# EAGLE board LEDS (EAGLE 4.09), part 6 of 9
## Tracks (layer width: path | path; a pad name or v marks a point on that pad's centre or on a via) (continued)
N$X.1430  (via drill 0.2)  (1 unrouted) (continued)
  Bottom 0.2: 39.44,35.76 38.85,36.35 38.41,36.35
  other vias: 39.44,35.83
N$X.1460  (via drill 0.2)  (1 unrouted)
  Bottom 0.2: 37.6,33.1 36.89,33.8 36.35,33.8
  other vias: 37.62,33.16
N$X.1461  (via drill 0.2)  (1 unrouted)
  Bottom 0.2: 37.53,35.8 36.89,36.44 36.63,36.44
  other vias: 37.57,35.78
N$X.1482  (via drill 0.2)  (1 unrouted)
  Bottom 0.2: 32.15,75 31.14,75.54 30.79,75.54
  other vias: 32.19,74.95
N$X.1491  (via drill 0.2)  (1 unrouted)
  Bottom 0.2: v35.82,33.14 35.14,33.83 34.72,33.83
N$X.1492  (via drill 0.2)  (1 unrouted)
  Bottom 0.2: v35.8,35.8 35.23,36.37 34.79,36.37
N$X.1522  (via drill 0.2)  (1 unrouted)
  Bottom 0.2: 33.93,33.14 33.21,33.87 32.9,33.87
  other vias: 33.98,33.14
N$X.1523  (via drill 0.2)  (1 unrouted)
  Bottom 0.2: 34.02,35.8 33.47,36.35 33.03,36.35
  other vias: 33.99,35.8
N$X.1553  (via drill 0.2)  (1 unrouted)
  Bottom 0.2: v32.22,33.14 31.47,33.89 31.21,33.89
N$X.1554  (via drill 0.2)  (1 unrouted)
  Bottom 0.2: 32.22,35.76 31.56,36.41 31.25,36.41
  other vias: 32.22,35.8
N$X.1555
  Bottom 0.2: 30.77,39.01 30.92,39.01
N$X.1575  (via drill 0.2)  (1 unrouted)
  Bottom 0.2: 33.99,75.02 33.45,75.57 32.59,75.57
  other vias: 34.01,74.94
N$X.1584  (via drill 0.2)  (2 unrouted)
  Bottom 0.2: 29.26,33.79 29.2,33.82 | 30.38,33.12 29.74,33.76 29.52,33.76
  other vias: 30.4,33.14
N$X.1585  (via drill 0.2)  (2 unrouted)
  Bottom 0.2: 29.21,36.43 29.58,36.43 | 30.4,35.84 29.85,36.39 29.48,36.39
  other vias: 30.42,35.84
N$X.1586
  Bottom 0.2: 29.27,39.07 29.42,39.07
N$X.1587
  Bottom 0.2: 28.97,41.72 29.19,41.72
N$X.1588  (via drill 0.2)  (1 unrouted)
  Bottom 0.2: 30.33,43.63 29.76,44.4 29.51,44.4
  other vias: 30.38,43.65
N$X.1589  (via drill 0.2)  (2 unrouted)
  Bottom 0.2: 29.67,46.89 29.25,46.94 | 30.41,46.15 29.13,46.94 29.36,46.94
  other vias: 30.43,46.15
N$X.1615  (via drill 0.2)  (1 unrouted)
  Bottom 0.2: 28.62,33.11 27.5,33.7 27.39,33.7
  other vias: 28.64,33.15
N$X.1616  (via drill 0.2)  (1 unrouted)
  Bottom 0.2: v28.6,35.81 27.48,36.43 27.33,36.43
N$X.1617  (via drill 0.2)  (1 unrouted)
  Bottom 0.2: 28.58,38.4 27.91,39.08 27.38,39.1
  other vias: 28.57,38.41
N$X.1618  (via drill 0.2)  (1 unrouted)
  Bottom 0.2: 28.54,41.05 27.33,41.8 27.47,41.77
  other vias: 28.57,41.03
N$X.1619  (via drill 0.2)  (1 unrouted)
  Bottom 0.2: 28.57,43.6 27.82,44.35 27.64,44.36
  other vias: 28.59,43.61
N$X.1620  (via drill 0.2)  (1 unrouted)
  Bottom 0.2: 28.66,46.16 27.27,46.96 27.17,46.96
  other vias: 28.64,46.17
N$X.1643  (via drill 0.2)  (1 unrouted)
  Bottom 0.2: 14.23,25.06 13.68,25.6 13.33,25.64
  other vias: 14.18,25.07
N$X.1646  (via drill 0.2)  (1 unrouted)
  Bottom 0.2: 26.75,33.14 25.69,33.8 25.69,33.9
  other vias: 26.77,33.14
N$X.1647  (via drill 0.2)  (1 unrouted)
  Bottom 0.2: v26.77,35.77 25.82,36.19 25.82,36.64
N$X.1648  (via drill 0.2)  (1 unrouted)
  Bottom 0.2: 26.8,38.4 26.31,38.89 25.81,39.04
  other vias: 26.77,38.41
N$X.1649  (via drill 0.2)  (1 unrouted)
  Bottom 0.2: v26.75,41.02 25.69,41.63 25.52,41.63
N$X.1650  (via drill 0.2)  (1 unrouted)
  Bottom 0.2: 26.79,43.6 25.65,44.26 25.55,44.26
  other vias: 26.8,43.61
N$X.1651  (via drill 0.2)  (1 unrouted)
  Bottom 0.2: 26.78,46.15 25.79,46.81 25.45,46.81
  other vias: 26.78,46.18
N$X.1677  (via drill 0.2)  (1 unrouted)
  Bottom 0.2: 24.96,33.13 24.14,33.48 24.14,33.92
  other vias: 24.97,33.14
N$X.1678  (via drill 0.2)  (1 unrouted)
  Bottom 0.2: 25,35.8 24.55,36.25 24.14,36.5
  other vias: 25.02,35.79
N$X.1679  (via drill 0.2)  (1 unrouted)
  Bottom 0.2: 25.06,38.39 24.54,38.92 24.02,39.05
  other vias: 25.02,38.43
N$X.1680  (via drill 0.2)  (1 unrouted)
  Bottom 0.2: 24.95,41 23.97,41.67 23.68,41.67
  other vias: 25,41.05
N$X.1681  (via drill 0.2)  (1 unrouted)
  Bottom 0.2: 24.94,43.61 24.04,44.22 23.79,44.22
  other vias: 25.01,43.59
N$X.1682  (via drill 0.2)  (1 unrouted)
  Bottom 0.2: 25.05,46.22 24.02,46.82 23.79,46.82
  other vias: 25.06,46.18
N$X.1708  (via drill 0.2)  (1 unrouted)
  Bottom 0.2: 23.23,33.12 22.22,33.78 22.06,33.78
  other vias: 23.22,33.14
N$X.1709  (via drill 0.2)  (1 unrouted)
  Bottom 0.2: 23.16,35.78 22.2,36.47 21.88,36.47
  other vias: 23.2,35.76
N$X.1710  (via drill 0.2)  (1 unrouted)
  Bottom 0.2: 23.15,38.4 22.17,39.09 21.93,39.09
  other vias: 23.19,38.4
N$X.1711  (via drill 0.2)  (1 unrouted)
  Bottom 0.2: 23.15,41.02 22.18,41.73 21.87,41.73
  other vias: 23.19,41.01
N$X.1712  (via drill 0.2)  (1 unrouted)
  Bottom 0.2: 23.15,43.63 22.21,44.27 22.06,44.27
  other vias: 23.19,43.63
N$X.1713  (via drill 0.2)  (1 unrouted)
  Bottom 0.2: 23.17,46.19 22.24,46.81 21.95,46.81
  other vias: 23.18,46.17
N$X.1739  (via drill 0.2)  (1 unrouted)
  Bottom 0.2: 21.34,33.15 20.51,33.81 20.21,33.81
  other vias: 21.38,33.14
N$X.1740  (via drill 0.2)  (1 unrouted)
  Bottom 0.2: 21.39,35.73 20.45,36.4 20.15,36.4
  other vias: 21.44,35.79
N$X.1741  (via drill 0.2)  (1 unrouted)
  Bottom 0.2: 21.09,38.42 20.4,39.11 20.21,39.11
  other vias: 21.33,38.4
N$X.1742  (via drill 0.2)  (1 unrouted)
  Bottom 0.2: 21.43,40.97 20.48,41.6 20.19,41.6
  other vias: 21.41,41.02
N$X.1743  (via drill 0.2)  (1 unrouted)
  Bottom 0.2: 21.45,43.64 20.41,44.33 20.02,44.33
  other vias: 21.4,43.62
N$X.1744  (via drill 0.2)  (1 unrouted)
  Bottom 0.2: 21.43,46.14 20.17,46.99 19.98,46.99
  other vias: 21.39,46.13
N$X.1770  (via drill 0.2)  (1 unrouted)
  Bottom 0.2: 19.58,33.13 18.52,33.87 18.38,33.87
  other vias: 19.61,33.14
N$X.1771  (via drill 0.2)  (1 unrouted)
  Bottom 0.2: 19.62,35.79 18.57,36.54 18.42,36.54
  other vias: 19.6,35.81
N$X.1772  (via drill 0.2)  (1 unrouted)
  Bottom 0.2: 19.55,38.41 18.68,39.01 18.5,39.01
  other vias: 19.58,38.41
N$X.1773  (via drill 0.2)  (1 unrouted)
  Bottom 0.2: 19.62,41.03 18.67,41.63 18.41,41.63
  other vias: 19.64,41.02
N$X.1774  (via drill 0.2)  (1 unrouted)
  Bottom 0.2: 19.77,43.52 18.72,44.31 18.36,44.31
  other vias: 19.59,43.63
N$X.1775  (via drill 0.2)  (1 unrouted)
  Bottom 0.2: 19.59,46.13 18.62,46.83 18.3,46.83
  other vias: 19.56,46.1
N$X.1801  (via drill 0.2)  (1 unrouted)
  Bottom 0.2: 17.78,33.16 16.85,33.86 16.79,33.86
  other vias: 17.79,33.13
N$X.1802  (via drill 0.2)  (1 unrouted)
  Bottom 0.2: 17.86,35.8 16.93,36.42 16.91,36.42
  other vias: 17.83,35.79
N$X.1803  (via drill 0.2)  (1 unrouted)
  Bottom 0.2: v17.6,38.43 16.88,39.15 16.88,39.3
N$X.1804  (via drill 0.2)  (1 unrouted)
  Bottom 0.2: 17.8,41.01 16.78,41.85 16.68,41.85
  other vias: 17.85,41.02
N$X.1805  (via drill 0.2)  (1 unrouted)
  Bottom 0.2: 17.81,43.57 16.93,44.27 16.72,44.27
  other vias: 17.82,43.63
N$X.1806  (via drill 0.2)  (1 unrouted)
  Bottom 0.2: 17.75,46.15 16.92,46.85 16.65,46.85
  other vias: 17.79,46.14
N$X.1832  (via drill 0.2)  (1 unrouted)
  Bottom 0.2: 16.09,33.09 15.44,33.75 15.09,33.78
  other vias: 16.09,33.12
N$X.1833  (via drill 0.2)  (1 unrouted)
  Bottom 0.2: 16.03,35.76 15.21,36.51 15.21,36.6
  other vias: 16.03,35.78
N$X.1834  (via drill 0.2)  (1 unrouted)
  Bottom 0.2: 15.88,38.42 15.29,39 15.29,39.15
  other vias: 16,38.41
N$X.1835  (via drill 0.2)  (1 unrouted)
  Bottom 0.2: 16.11,40.95 15.49,41.57 15.01,41.65
  other vias: 16.04,41.02
N$X.1836  (via drill 0.2)  (1 unrouted)
  Bottom 0.2: 15.88,43.69 15.27,44.3 15.27,44.31
  other vias: 16,43.62
N$X.1837  (via drill 0.2)  (1 unrouted)
  Bottom 0.2: 16.05,46.1 15.47,46.69 15.04,46.77
  other vias: 16.01,46.16
N$X.1863
  Bottom 0.2: 14.12,33.15 13.34,33.92 13.3,33.92
N$X.1864  (via drill 0.2)  (1 unrouted)
  Bottom 0.2: 14.14,35.79 13.44,36.49 13.31,36.49
  other vias: 14.17,35.77
N$X.1865  (via drill 0.2)  (1 unrouted)
  Bottom 0.2: 14.2,38.42 13.36,39.26 13.35,39.26
  other vias: 14.2,38.44
N$X.1866  (via drill 0.2)  (1 unrouted)
  Bottom 0.2: 14.14,41.08 13.46,41.77 13.29,41.77
  other vias: 14.17,41.05
N$X.1867  (via drill 0.2)  (1 unrouted)
  Bottom 0.2: v14.2,43.63 13.56,44.27 13.34,44.27
N$X.1868  (via drill 0.2)  (1 unrouted)
  Bottom 0.2: 14.13,46.18 13.51,46.81 13.31,46.81
  other vias: 14.18,46.2
N$X.1894  (via drill 0.2)  (1 unrouted)
  Bottom 0.2: 12.38,33.16 11.84,33.7 11.67,33.7
  other vias: 12.43,33.14
N$X.1895  (via drill 0.2)  (1 unrouted)
  Bottom 0.2: 12.42,35.8 11.81,36.41 11.48,36.41
  other vias: 12.42,35.83
N$X.1896  (via drill 0.2)  (1 unrouted)
  Bottom 0.2: 12.41,38.47 11.81,39.06 11.31,39.06
  other vias: 12.41,38.49
N$X.1897  (via drill 0.2)  (1 unrouted)
  Bottom 0.2: 12.42,41.01 11.75,41.68 11.2,41.68
  other vias: 12.41,41.05
N$X.1898  (via drill 0.2)  (1 unrouted)
  Bottom 0.2: 12.34,43.69 11.67,44.36 11.42,44.36
  other vias: 12.35,43.66
N$X.1899  (via drill 0.2)  (1 unrouted)
  Bottom 0.2: 12.37,46.18 11.77,46.78 11.44,46.78
  other vias: 12.36,46.21
N$X.1925  (via drill 0.2)  (1 unrouted)
  Bottom 0.2: v10.6,33.18 9.99,33.79 9.65,33.79
N$X.1926  (via drill 0.2)  (1 unrouted)
  Bottom 0.2: 10.61,35.85 10,36.46 9.7,36.46
  other vias: 10.62,35.83
N$X.1927  (via drill 0.2)  (1 unrouted)
  Bottom 0.2: 10.56,38.43 9.91,39.08 9.61,39.08
  other vias: 10.58,38.43
N$X.1928  (via drill 0.2)  (1 unrouted)
  Bottom 0.2: 10.62,41.04 9.95,41.72 9.44,41.72
  other vias: 10.59,41.05
N$X.1929  (via drill 0.2)  (1 unrouted)
  Bottom 0.2: 10.58,43.65 9.86,44.37 9.69,44.37
  other vias: 10.57,43.69
N$X.1930  (via drill 0.2)  (1 unrouted)
  Bottom 0.2: 10.65,46.24 9.9,46.99 9.74,46.99
  other vias: 10.59,46.24
N$X.1953  (via drill 0.2)  (1 unrouted)
  Bottom 0.2: 3.61,25.12 3.07,25.67 2.72,25.67
  other vias: 3.57,25.1
N$X.1956  (via drill 0.2)  (1 unrouted)
  Bottom 0.2: 8.74,33.13 8.21,33.66 8.04,33.66
  other vias: 8.81,33.13
N$X.1957  (via drill 0.2)  (1 unrouted)
  Bottom 0.2: 8.92,35.81 8.29,36.45 7.59,36.45
  other vias: 8.85,35.77
N$X.1958  (via drill 0.2)  (1 unrouted)
  Bottom 0.2: 8.82,38.39 8.05,39.15 7.92,39.23
  other vias: 8.81,38.42
N$X.1959  (via drill 0.2)  (1 unrouted)
  Bottom 0.2: 8.78,40.98 8.14,41.61 7.99,41.61
  other vias: 8.78,41.05
N$X.1960  (via drill 0.2)  (1 unrouted)
  Bottom 0.2: 8.81,43.67 8.19,44.29 7.83,44.29
  other vias: 8.81,43.64
N$X.1961  (via drill 0.2)  (1 unrouted)
  Bottom 0.2: 8.81,46.21 8.13,46.88 7.94,46.88
  other vias: 8.81,46.25
N$X.1987  (via drill 0.2)  (1 unrouted)
  Bottom 0.2: 7.11,33.12 6.39,33.83 6.23,33.83
  other vias: 7.04,33.13
N$X.1988  (via drill 0.2)  (1 unrouted)
  Bottom 0.2: 6.98,35.8 6.09,36.68 5.9,36.68
  other vias: 7.08,35.8
N$X.1989  (via drill 0.2)
  Bottom 0.2: v7.05,38.43 6.39,39.09 6.12,39.09
N$X.1990  (via drill 0.2)  (1 unrouted)
  Bottom 0.2: 7.05,41.03 6.37,41.72 5.9,41.72
  other vias: 7.06,41.06
N$X.1991  (via drill 0.2)  (1 unrouted)
  Bottom 0.2: v7,43.62 6.38,44.24 5.89,44.24
N$X.1992  (via drill 0.2)  (1 unrouted)
  Bottom 0.2: 7,46.16 6.25,46.9 6.17,46.9
  other vias: 6.98,46.21
N$X.2018  (via drill 0.2)  (1 unrouted)
  Bottom 0.2: 5.25,33.13 4.62,33.75 4.43,33.75
  other vias: 5.27,33.13
N$X.2019  (via drill 0.2)  (1 unrouted)
  Bottom 0.2: 5.31,35.86 4.61,36.56 4.5,36.56
  other vias: 5.2,35.81
N$X.2020  (via drill 0.2)
  Bottom 0.2: v5.3,38.4 4.68,39.02 4.5,39.09
N$X.2021  (via drill 0.2)  (1 unrouted)
  Bottom 0.2: 5.29,41.03 4.67,41.65 4.43,41.65
  other vias: 5.27,41.05
N$X.2022  (via drill 0.2)  (1 unrouted)
  Bottom 0.2: 5.29,43.66 4.67,44.27 4.52,44.27
  other vias: 5.28,43.64
N$X.2023  (via drill 0.2)  (1 unrouted)
  Bottom 0.2: 5.23,46.17 4.61,46.79 4.61,46.85
  other vias: 5.25,46.2
N$X.2027  (via drill 0.2)  (1 unrouted)
  Bottom 0.2: 3.53,48.8 2.99,49.34 2.64,49.34
  other vias: 3.47,48.73
N$X.2049  (via drill 0.2)  (1 unrouted)
  Bottom 0.2: 3.55,33.09 2.8,33.84 2.79,33.84
  other vias: 3.56,33.15
N$X.2050  (via drill 0.2)  (1 unrouted)
  Bottom 0.2: 3.56,35.79 2.79,36.56 2.77,36.56
  other vias: 3.46,35.8
N$X.2051  (via drill 0.2)  (1 unrouted)
  Bottom 0.2: 3.49,38.42 2.73,39.17 2.73,39.27
  other vias: 3.5,38.45
N$X.2052  (via drill 0.2)  (1 unrouted)
  Bottom 0.2: 3.46,41.02 2.85,41.62 2.85,41.7
  other vias: 3.47,41.06
N$X.2053  (via drill 0.2)  (1 unrouted)
  Bottom 0.2: 3.49,43.6 2.89,44.19 2.7,44.19
  other vias: 3.49,43.64
N$X.2054  (via drill 0.2)  (1 unrouted)
  Bottom 0.2: 3.29,46.21 2.63,46.87 2.55,46.87
  other vias: 3.44,46.17
N$X.2063  (via drill 0.2)  (1 unrouted)
  Bottom 0.2: 3.51,59.42 2.97,59.96 2.62,59.96
  other vias: 3.47,59.4
N$X.2076  (via drill 0.2)  (1 unrouted)
  Bottom 0.2: 112.05,30.65 111.5,31.19 111.16,31.19
  other vias: 112,30.63
N$X.2077  (via drill 0.2)  (1 unrouted)
  Bottom 0.2: 110.3,30.62 109.76,31.17 109.41,31.17
  other vias: 110.26,30.6
N$X.2078
  Bottom 0.2: 110.3,30.62 109.76,31.17 109.41,31.17
N$X.2079  (via drill 0.2)  (1 unrouted)
  Bottom 0.2: 108.52,30.61 107.97,31.16 107.62,31.16
  other vias: 108.47,30.59
N$X.2080  (via drill 0.2)  (1 unrouted)
  Bottom 0.2: 106.82,30.61 106.28,31.16 105.92,31.16
  other vias: 106.78,30.59
N$X.2081  (via drill 0.2)  (1 unrouted)
  Bottom 0.2: 105.03,30.62 104.48,31.17 104.14,31.17
  other vias: 104.98,30.6
N$X.2082  (via drill 0.2)  (1 unrouted)
  Bottom 0.2: 103.27,30.61 102.72,31.16 102.38,31.16
  other vias: 103.22,30.59
N$X.2083  (via drill 0.2)  (1 unrouted)
  Bottom 0.2: 103.26,27.85 102.72,28.4 102.36,28.4
  other vias: 103.26,27.87
N$X.2084  (via drill 0.2)  (1 unrouted)
  Bottom 0.2: 105.07,27.87 104.53,28.41 104.17,28.41
  other vias: 105.03,27.85
N$X.2085  (via drill 0.2)  (1 unrouted)
  Bottom 0.2: 106.82,27.8 106.28,28.35 105.92,28.35
  other vias: 106.76,27.85
N$X.2086  (via drill 0.2)  (1 unrouted)
  Bottom 0.2: 108.58,27.87 108.03,28.41 107.69,28.41
  other vias: 108.53,27.85
N$X.2087  (via drill 0.2)  (1 unrouted)
  Bottom 0.2: 110.33,27.89 109.78,28.44 109.44,28.44
  other vias: 110.28,27.87
N$X.2088  (via drill 0.2)  (1 unrouted)
  Bottom 0.2: 112.11,27.87 111.56,28.41 111.21,28.41
  other vias: 112.06,27.85
N$X.2089  (via drill 0.2)  (1 unrouted)
  Bottom 0.2: 101.51,30.62 100.97,31.17 100.61,31.17
  other vias: 101.47,30.6
N$X.2090  (via drill 0.2)  (1 unrouted)
  Bottom 0.2: 99.79,30.61 99.25,31.16 98.89,31.16
  other vias: 99.75,30.59
N$X.2091  (via drill 0.2)  (1 unrouted)
  Bottom 0.2: 98.05,30.61 97.5,31.16 97.16,31.16
  other vias: 98,30.59
N$X.2092  (via drill 0.2)  (1 unrouted)
  Bottom 0.2: 96.33,30.65 95.78,31.19 95.44,31.19
  other vias: 96.28,30.63
N$X.2093  (via drill 0.2)  (1 unrouted)
  Bottom 0.2: 94.59,30.61 94.05,31.16 93.7,31.16
  other vias: 94.55,30.59
N$X.2094  (via drill 0.2)  (1 unrouted)
  Bottom 0.2: 92.82,30.62 92.28,31.17 91.92,31.17
  other vias: 92.78,30.6
N$X.2095  (via drill 0.2)  (1 unrouted)
  Bottom 0.2: 92.84,27.85 92.3,28.4 91.95,28.4
  other vias: 92.8,27.85
N$X.2096  (via drill 0.2)  (1 unrouted)
  Bottom 0.2: 94.62,27.9 94.08,28.45 93.72,28.45
  other vias: 94.58,27.88
N$X.2097  (via drill 0.2)  (1 unrouted)
  Bottom 0.2: 96.34,27.89 95.8,28.44 95.45,28.44
  other vias: 96.3,27.87
N$X.2098  (via drill 0.2)  (1 unrouted)
  Bottom 0.2: 98.08,27.89 97.53,28.44 97.19,28.44
  other vias: 98.03,27.87
N$X.2099  (via drill 0.2)  (1 unrouted)
  Bottom 0.2: 99.86,27.89 99.32,28.44 98.97,28.44
  other vias: 99.82,27.87
N$X.2100  (via drill 0.2)  (1 unrouted)
  Bottom 0.2: 101.58,27.9 101.03,28.45 100.68,28.45
  other vias: 101.53,27.88
N$X.2101  (via drill 0.2)  (1 unrouted)
  Bottom 0.2: 91.28,30.62 90.73,31.17 90.39,31.17
  other vias: 91.11,30.62
N$X.2102  (via drill 0.2)  (1 unrouted)
  Bottom 0.2: 89.35,30.62 88.8,31.17 88.45,31.17
  other vias: 89.3,30.6
N$X.2103  (via drill 0.2)  (1 unrouted)
  Bottom 0.2: 91.25,27.89 90.71,28.44 90.36,28.44
  other vias: 91.06,27.89
N$X.2104  (via drill 0.2)  (1 unrouted)
  Bottom 0.2: 89.36,27.89 88.82,28.44 88.47,28.44
  other vias: 89.32,27.87
N$X.2105  (via drill 0.2)  (1 unrouted)
  Bottom 0.2: 87.6,30.64 87.05,31.18 86.7,31.18
  other vias: 87.55,30.62
N$X.2106  (via drill 0.2)  (1 unrouted)
  Bottom 0.2: 87.53,27.89 86.99,28.44 86.64,28.44
  other vias: 87.49,27.87
N$X.2107  (via drill 0.2)  (1 unrouted)
  Bottom 0.2: 85.88,30.64 85.33,31.18 84.98,31.18
  other vias: 85.83,30.62
N$X.2108  (via drill 0.2)  (1 unrouted)
  Bottom 0.2: 84.09,30.62 83.55,31.17 83.2,31.17
  other vias: 84.05,30.6
N$X.2109  (via drill 0.2)  (1 unrouted)
  Bottom 0.2: 82.32,30.65 81.78,31.19 81.42,31.19
  other vias: 82.28,30.63
N$X.2110  (via drill 0.2)  (1 unrouted)
  Bottom 0.2: 80.58,30.65 80.04,31.19 79.69,31.19
  other vias: 80.54,30.63
N$X.2111  (via drill 0.2)  (1 unrouted)
  Bottom 0.2: 80.58,27.88 80.04,28.42 79.69,28.42
  other vias: 80.54,27.86
N$X.2112  (via drill 0.2)  (1 unrouted)
  Bottom 0.2: 82.33,27.85 81.78,28.4 81.44,28.4
  other vias: 82.28,27.87
N$X.2113  (via drill 0.2)  (1 unrouted)
  Bottom 0.2: 84.13,27.88 83.58,28.42 83.23,28.42
  other vias: 84.08,27.86
N$X.2114  (via drill 0.2)  (1 unrouted)
  Bottom 0.2: 85.83,27.89 85.28,28.44 84.94,28.44
  other vias: 85.78,27.87
N$X.2115  (via drill 0.2)  (1 unrouted)
  Bottom 0.2: 78.85,30.65 78.3,31.19 77.95,31.19
  other vias: 78.8,30.63
N$X.2116  (via drill 0.2)  (1 unrouted)
  Bottom 0.2: 77.06,30.62 76.52,31.17 76.16,31.17
  other vias: 77.02,30.6
N$X.2117  (via drill 0.2)  (1 unrouted)
  Bottom 0.2: 75.3,30.65 74.75,31.19 74.41,31.19
  other vias: 75.25,30.63
N$X.2118  (via drill 0.2)  (1 unrouted)
  Bottom 0.2: 73.56,30.64 73.02,31.18 72.67,31.18
  other vias: 73.52,30.62
N$X.2119  (via drill 0.2)  (1 unrouted)
  Bottom 0.2: 71.84,30.66 71.3,31.21 70.94,31.21
  other vias: 71.75,30.6
N$X.2120  (via drill 0.2)  (1 unrouted)
  Bottom 0.2: 70.03,30.64 69.48,31.18 69.14,31.18
  other vias: 69.98,30.62
N$X.2121  (via drill 0.2)  (1 unrouted)
  Bottom 0.2: 70.07,27.85 69.53,28.4 69.17,28.4
  other vias: 70.03,27.83
N$X.2122  (via drill 0.2)  (1 unrouted)
  Bottom 0.2: 71.77,27.87 71.22,28.41 70.87,28.41
  other vias: 71.72,27.85
N$X.2123  (via drill 0.2)  (1 unrouted)
  Bottom 0.2: 73.59,27.88 73.05,28.42 72.69,28.42
  other vias: 73.55,27.86
N$X.2124  (via drill 0.2)  (1 unrouted)
  Bottom 0.2: 75.3,27.88 74.75,28.42 74.41,28.42
  other vias: 75.25,27.86
N$X.2125  (via drill 0.2)  (1 unrouted)
  Bottom 0.2: 77.08,27.88 76.53,28.42 76.18,28.42
  other vias: 77.03,27.86
N$X.2126  (via drill 0.2)  (1 unrouted)
  Bottom 0.2: 78.83,27.89 78.29,28.44 77.94,28.44
  other vias: 78.79,27.87
N$X.2127
  Bottom 0.2: 65.99,31.14 65.64,31.14
N$X.2128  (via drill 0.2)  (1 unrouted)
  Bottom 0.2: 68.28,30.6 67.73,31.14 67.39,31.14
  other vias: 68.23,30.58
N$X.2129  (via drill 0.2)  (1 unrouted)
  Bottom 0.2: 68.3,27.89 67.75,28.44 67.4,28.44
  other vias: 68.25,27.87
N$X.2130
  Bottom 0.2: 66,28.41 65.65,28.41
N$X.2131
  Bottom 0.2: 64.25,28.44 63.91,28.44
N$X.2133
  Bottom 0.2: 64.2,31.17 63.85,31.17
N$X.2160  (via drill 0.2)  (1 unrouted)
  Bottom 0.2: 39.4,30.55 38.69,31.26 38.45,31.26
  other vias: 39.38,30.57
N$X.2161  (via drill 0.2)  (1 unrouted)
  Bottom 0.2: 39.46,27.88 38.8,28.54 38.48,28.54
  other vias: 39.43,27.89
N$X.2162  (via drill 0.2)  (1 unrouted)
  Bottom 0.2: 37.66,30.53 36.98,31.21 36.72,31.21
  other vias: 37.62,30.62
N$X.2163  (via drill 0.2)  (1 unrouted)
  Bottom 0.2: 37.57,27.88 36.98,28.47 36.72,28.47
  other vias: 37.59,27.87
N$X.2164  (via drill 0.2)  (1 unrouted)
  Bottom 0.2: 35.91,30.64 35.29,31.26 34.85,31.26
  other vias: 35.84,30.62
N$X.2165  (via drill 0.2)  (1 unrouted)
  Bottom 0.2: 35.73,27.88 34.88,28.73 34.72,28.73
  other vias: 35.77,27.88
N$X.2166  (via drill 0.2)  (1 unrouted)
  Bottom 0.2: 34,30.6 33.4,31.19 33.19,31.19
  other vias: 33.99,30.62
N$X.2167  (via drill 0.2)  (1 unrouted)
  Bottom 0.2: 34.04,27.88 33.32,28.6 32.99,28.6
  other vias: 33.99,27.9
N$X.2168  (via drill 0.2)  (1 unrouted)
  Bottom 0.2: 32.22,30.62 31.58,31.26 31.19,31.26
  other vias: 32.19,30.62
N$X.2169  (via drill 0.2)  (2 unrouted)
  Bottom 0.2: 31.11,28.41 30.77,28.41 | 32.15,27.83 31.36,28.62 31.21,28.62
  other vias: 32.17,27.84
N$X.2170  (via drill 0.2)  (2 unrouted)
  Bottom 0.2: 29.52,31.19 29.17,31.19 | 30.4,30.62 29.74,31.28 29.5,31.28
  other vias: 30.4,30.59
N$X.2171  (via drill 0.2)  (1 unrouted)
  Bottom 0.2: 30.4,27.88 29.67,28.6 29.48,28.6
  other vias: 30.41,27.89
N$X.2172  (via drill 0.2)  (1 unrouted)
  Bottom 0.2: 28.54,27.88 27.52,28.41 27.5,28.43
  other vias: 28.58,27.86
N$X.2173  (via drill 0.2)  (1 unrouted)
  Bottom 0.2: 28.66,30.58 27.55,31.14 27.2,31.14
  other vias: 28.62,30.58
N$X.2174  (via drill 0.2)  (1 unrouted)
  Bottom 0.2: v26.76,30.6 25.82,31.18 25.47,31.18
N$X.2175  (via drill 0.2)  (1 unrouted)
  Bottom 0.2: 26.78,27.89 25.84,28.41 25.49,28.41
  other vias: 26.81,27.85
N$X.2176  (via drill 0.2)  (1 unrouted)
  Bottom 0.2: 24.98,27.87 24.04,28.42 23.7,28.42
  other vias: 25,27.86
N$X.2177  (via drill 0.2)  (1 unrouted)
  Bottom 0.2: 24.95,30.61 24.04,31.17 23.7,31.17
  other vias: 24.99,30.6
N$X.2178  (via drill 0.2)  (1 unrouted)
  Bottom 0.2: 23.16,30.59 22.31,31.19 21.96,31.19
  other vias: 23.19,30.6
N$X.2179  (via drill 0.2)  (1 unrouted)
  Bottom 0.2: 23.2,27.89 22.29,28.45 21.95,28.45
  other vias: 23.26,27.87
N$X.2180  (via drill 0.2)  (1 unrouted)
  Bottom 0.2: 21.35,27.87 20.8,28.41 20.17,28.45
  other vias: 21.37,27.86
N$X.2181  (via drill 0.2)  (1 unrouted)
  Bottom 0.2: 21.37,30.61 20.56,31.18 20.21,31.18
  other vias: 21.39,30.6
N$X.2182  (via drill 0.2)  (1 unrouted)
  Bottom 0.2: 19.67,30.59 19.13,31.14 18.43,31.19
  other vias: 19.61,30.59
N$X.2183  (via drill 0.2)  (1 unrouted)
  Bottom 0.2: 19.52,27.86 18.98,28.4 18.45,28.41
  other vias: 19.58,27.84
N$X.2184  (via drill 0.2)  (1 unrouted)
  Bottom 0.2: 17.78,27.89 17.23,28.43 16.72,28.42
  other vias: 17.79,27.87
N$X.2185  (via drill 0.2)  (1 unrouted)
  Bottom 0.2: 17.86,30.59 17.31,31.13 16.77,31.14
  other vias: 17.87,30.59
N$X.2186  (via drill 0.2)  (1 unrouted)
  Bottom 0.2: 15.93,30.61 15.37,31.16 15.02,31.16
  other vias: 16.04,30.59
N$X.2187  (via drill 0.2)  (1 unrouted)
  Bottom 0.2: 16.03,27.85 15.48,28.4 15.04,28.4
  other vias: 16.01,27.86
N$X.2188  (via drill 0.2)  (1 unrouted)
  Bottom 0.2: 14.21,30.61 13.67,31.16 13.32,31.16
  other vias: 14.17,30.59
N$X.2189  (via drill 0.2)  (1 unrouted)
  Bottom 0.2: 12.43,30.65 11.88,31.19 11.54,31.19
  other vias: 12.33,30.59
N$X.2190  (via drill 0.2)  (1 unrouted)
  Bottom 0.2: 10.67,30.61 10.12,31.16 9.78,31.16
  other vias: 10.62,30.59
N$X.2191  (via drill 0.2)  (1 unrouted)
  Bottom 0.2: 8.9,30.6 8.35,31.14 8,31.14
  other vias: 8.85,30.58
N$X.2192  (via drill 0.2)  (1 unrouted)
  Bottom 0.2: 7.12,30.65 6.58,31.19 6.22,31.19
  other vias: 7.05,30.6
N$X.2193  (via drill 0.2)  (1 unrouted)
  Bottom 0.2: 5.3,30.6 4.76,31.14 4.41,31.14
  other vias: 5.17,30.59
N$X.2194  (via drill 0.2)  (1 unrouted)
  Bottom 0.2: 5.23,27.93 4.68,28.47 4.45,28.46
  other vias: 5.24,27.9
N$X.2195  (via drill 0.2)  (1 unrouted)
  Bottom 0.2: 7.12,27.88 6.58,28.42 6.22,28.42
  other vias: 7.08,27.86
N$X.2196  (via drill 0.2)  (1 unrouted)
  Bottom 0.2: 8.88,27.9 8.34,28.45 7.98,28.45
  other vias: 8.78,27.86
N$X.2197  (via drill 0.2)  (1 unrouted)
  Bottom 0.2: 10.71,27.94 10.16,28.49 9.81,28.49
  other vias: 10.66,27.87
N$X.2198  (via drill 0.2)  (1 unrouted)
  Bottom 0.2: 12.54,27.89 12,28.44 11.65,28.44
  other vias: 12.5,27.87
N$X.2199  (via drill 0.2)  (1 unrouted)
  Bottom 0.2: 14.28,27.9 13.74,28.45 13.38,28.45
  other vias: 14.24,27.88
N$X.2200  (via drill 0.2)  (1 unrouted)
  Bottom 0.2: 3.46,30.64 2.92,31.18 2.72,31.19
  other vias: 3.48,30.58
N$X.2201  (via drill 0.2)  (1 unrouted)
  Bottom 0.2: 3.5,27.9 2.95,28.45 2.8,28.44
  other vias: 3.52,27.85
N$X.2202  (via drill 0.2)  (1 unrouted)
  Bottom 0.2: 3.47,22.44 2.92,22.98 2.74,22.96
  other vias: 3.46,22.45
N$X.2203  (via drill 0.2)  (1 unrouted)
  Bottom 0.2: 3.48,19.92 2.93,20.46 2.77,20.49
  other vias: 3.49,19.9
N$X.2204  (via drill 0.2)  (1 unrouted)
  Bottom 0.2: v5.27,25.09 4.72,25.64 4.54,25.64
N$X.2205  (via drill 0.2)  (1 unrouted)
  Bottom 0.2: 5.27,22.49 4.72,23.04 4.51,23.05
  other vias: 5.27,22.46
N$X.2206  (via drill 0.2)  (1 unrouted)
  Bottom 0.2: 5.21,19.92 4.66,20.46 4.46,20.5
  other vias: 5.23,19.9
N$X.2207  (via drill 0.2)  (1 unrouted)
  Bottom 0.2: 7.05,19.92 6.5,20.46 6.25,20.47
  other vias: 7.03,19.9
N$X.2208  (via drill 0.2)  (1 unrouted)
  Bottom 0.2: 7.02,22.46 6.47,23 6.26,23.01
  other vias: 7.01,22.44
N$X.2209  (via drill 0.2)  (1 unrouted)
  Bottom 0.2: 7.17,25.11 6.62,25.65 6.27,25.65
  other vias: 7.12,25.09
N$X.2210  (via drill 0.2)  (1 unrouted)
  Bottom 0.2: 8.96,25.11 8.42,25.65 8.06,25.65
  other vias: 8.89,25.05
N$X.2211  (via drill 0.2)  (1 unrouted)
  Bottom 0.2: 8.87,22.5 8.33,23.05 7.97,23.05
  other vias: 8.83,22.48
N$X.2212  (via drill 0.2)  (1 unrouted)
  Bottom 0.2: 8.88,19.94 8.34,20.49 7.98,20.49
  other vias: 8.84,19.92
N$X.2213  (via drill 0.2)  (1 unrouted)
  Bottom 0.2: 10.7,25.09 10.15,25.64 9.8,25.64
  other vias: 10.65,25.07
N$X.2214  (via drill 0.2)  (1 unrouted)
  Bottom 0.2: 10.76,22.52 10.21,23.06 9.87,23.06
  other vias: 10.65,22.44
N$X.2215  (via drill 0.2)  (1 unrouted)
  Bottom 0.2: 10.76,19.93 10.21,20.47 9.87,20.47
  other vias: 10.66,19.88
N$X.2216  (via drill 0.2)  (1 unrouted)
  Bottom 0.2: 12.51,19.94 11.96,20.49 11.61,20.49
  other vias: 12.4,19.9
N$X.2217  (via drill 0.2)  (1 unrouted)
  Bottom 0.2: 12.5,22.49 11.95,23.04 11.6,23.04
  other vias: 12.45,22.47
N$X.2218  (via drill 0.2)  (1 unrouted)
  Bottom 0.2: 12.51,25.12 11.96,25.67 11.61,25.67
  other vias: 12.46,25.1
N$X.2219  (via drill 0.2)  (1 unrouted)
  Bottom 0.2: 3.35,9.62 2.81,10.17 2.46,10.17
  other vias: 3.31,9.6
N$X.2220  (via drill 0.2)  (1 unrouted)
  Bottom 0.2: 3.38,6.99 2.84,7.54 2.49,7.54
  other vias: 3.34,6.97
N$X.2221  (via drill 0.2)  (1 unrouted)
  Bottom 0.2: 3.42,4.32 2.87,4.87 2.52,4.87
  other vias: 3.37,4.3
N$X.2222  (via drill 0.2)  (1 unrouted)
  Bottom 0.2: 5.14,4.31 4.59,4.86 4.25,4.86
  other vias: 5.09,4.29
N$X.2223  (via drill 0.2)  (1 unrouted)
  Bottom 0.2: 5.15,6.97 4.6,7.51 4.25,7.51
  other vias: 5.1,6.95
N$X.2224  (via drill 0.2)  (1 unrouted)
  Bottom 0.2: 5.15,9.59 4.6,10.14 4.25,10.14
  other vias: 5.1,9.57
N$X.2225  (via drill 0.2)  (1 unrouted)
  Bottom 0.2: 6.98,9.61 6.43,10.15 6.08,10.15
  other vias: 6.93,9.59
N$X.2226  (via drill 0.2)  (1 unrouted)
  Bottom 0.2: 6.88,7 6.34,7.55 5.99,7.55
  other vias: 6.84,6.98
N$X.2227  (via drill 0.2)  (1 unrouted)
  Bottom 0.2: 6.88,4.35 6.34,4.89 5.99,4.89
  other vias: 6.84,4.33
N$X.2228  (via drill 0.2)  (1 unrouted)
  Bottom 0.2: 8.69,4.34 8.14,4.88 7.79,4.88
  other vias: 8.81,4.29
N$X.2229  (via drill 0.2)  (1 unrouted)
  Bottom 0.2: 8.7,6.99 8.15,7.54 7.8,7.54
  other vias: 8.74,6.91
N$X.2230  (via drill 0.2)  (1 unrouted)
  Bottom 0.2: 8.69,9.62 8.14,10.17 7.79,10.17
  other vias: 8.75,9.55
N$X.2231  (via drill 0.2)  (1 unrouted)
  Bottom 0.2: 10.44,9.62 9.89,10.17 9.54,10.17
  other vias: 10.59,9.54
N$X.2232  (via drill 0.2)  (1 unrouted)
  Bottom 0.2: 10.46,6.98 9.92,7.52 9.57,7.52
  other vias: 10.65,6.93
N$X.2233  (via drill 0.2)  (1 unrouted)
  Bottom 0.2: 10.48,4.31 9.93,4.86 9.58,4.86
  other vias: 10.61,4.29
N$X.2234  (via drill 0.2)  (1 unrouted)
  Bottom 0.2: 3.51,17.34 2.97,17.89 2.8,17.9
  other vias: 3.52,17.3
N$X.2235  (via drill 0.2)  (1 unrouted)
  Bottom 0.2: 3.46,14.77 3.13,15.4 2.82,15.4
  other vias: 3.47,14.78
N$X.2236  (via drill 0.2)  (1 unrouted)
  Bottom 0.2: 3.62,12.2 2.84,12.78 2.49,12.78
  other vias: 3.65,12.22
N$X.2237  (via drill 0.2)  (1 unrouted)
  Bottom 0.2: 5.28,17.35 4.74,17.89 4.55,17.92
  other vias: 5.33,17.35
N$X.2238  (via drill 0.2)  (1 unrouted)
  Bottom 0.2: 5.25,14.8 4.7,15.35 4.53,15.38
  other vias: 5.27,14.78
N$X.2239  (via drill 0.2)  (1 unrouted)
  Bottom 0.2: 5.32,12.22 4.62,12.77 4.27,12.77
  other vias: 5.38,12.23
N$X.2240  (via drill 0.2)  (1 unrouted)
  Bottom 0.2: 7.03,12.24 6.48,12.78 5.98,12.78
  other vias: 7.05,12.22
N$X.2241  (via drill 0.2)  (1 unrouted)
  Bottom 0.2: v7.06,14.82 6.51,15.36 6.2,15.37
N$X.2242  (via drill 0.2)  (1 unrouted)
  Bottom 0.2: 7.17,17.31 6.62,17.86 6.27,17.86
  other vias: 7.08,17.31
N$X.2243  (via drill 0.2)  (1 unrouted)
  Bottom 0.2: 8.9,17.38 8.35,17.92 8,17.92
  other vias: 8.85,17.36
N$X.2244  (via drill 0.2)  (1 unrouted)
  Bottom 0.2: 8.88,14.86 8.34,15.41 7.98,15.41
  other vias: 8.84,14.84
N$X.2245  (via drill 0.2)  (1 unrouted)
  Bottom 0.2: 8.75,12.25 8.21,12.79 7.85,12.79
  other vias: 8.71,12.19
N$X.2246  (via drill 0.2)  (1 unrouted)
  Bottom 0.2: 10.79,17.36 10.24,17.91 9.89,17.91
  other vias: 10.74,17.34
N$X.2247  (via drill 0.2)  (1 unrouted)
  Bottom 0.2: 10.79,14.85 10.24,15.4 9.89,15.4
  other vias: 10.74,14.83
N$X.2248  (via drill 0.2)  (1 unrouted)
  Bottom 0.2: 10.49,12.25 9.94,12.79 9.59,12.79
  other vias: 10.44,12.23
N$X.2249  (via drill 0.2)  (1 unrouted)
  Bottom 0.2: 12.54,17.36 11.99,17.91 11.64,17.91
  other vias: 12.49,17.34
N$X.2250  (via drill 0.2)  (1 unrouted)
  Bottom 0.2: 12.6,14.79 12.06,15.33 11.71,15.33
  other vias: 12.56,14.81
N$X.2251  (via drill 0.2)  (1 unrouted)
  Bottom 0.2: 12.45,12.2 11.9,12.74 11.55,12.74
  other vias: 12.4,12.18
N$X.2252  (via drill 0.2)  (1 unrouted)
  Bottom 0.2: 14.09,17.34 13.54,17.88 13.19,17.88
  other vias: 14.16,17.32
N$X.2253  (via drill 0.2)  (1 unrouted)
  Bottom 0.2: 15.92,17.35 15.37,17.9 15.02,17.9
  other vias: 15.99,17.29
N$X.2254  (via drill 0.2)  (1 unrouted)
  Bottom 0.2: 17.84,17.2 17.29,17.75 16.6,17.87
  other vias: 17.77,17.3
N$X.2255  (via drill 0.2)  (1 unrouted)
  Bottom 0.2: 19.57,17.28 19.02,17.83 18.2,17.87
  other vias: 19.58,17.3
N$X.2256  (via drill 0.2)  (1 unrouted)
  Bottom 0.2: 21.23,17.28 20.34,17.87 19.99,17.87
  other vias: 21.37,17.28
N$X.2257  (via drill 0.2)  (1 unrouted)
  Bottom 0.2: 23.15,17.32 22.06,17.9 21.71,17.9
  other vias: 23.18,17.3
N$X.2258  (via drill 0.2)  (1 unrouted)
  Bottom 0.2: 23.22,14.79 22.16,15.31 21.81,15.31
  other vias: 23.21,14.78
N$X.2259  (via drill 0.2)  (1 unrouted)
  Bottom 0.2: 21.35,14.74 20.51,15.33 20.16,15.33
  other vias: 21.38,14.81
N$X.2260  (via drill 0.2)  (1 unrouted)
  Bottom 0.2: 19.6,14.76 19.05,15.31 18.47,15.34
  other vias: 19.6,14.81
N$X.2261  (via drill 0.2)  (1 unrouted)
  Bottom 0.2: 17.82,14.75 17.28,15.29 16.71,15.36
  other vias: 17.82,14.81
N$X.2262  (via drill 0.2)  (1 unrouted)
  Bottom 0.2: 16.08,14.72 15.53,15.27 15.03,15.33
  other vias: 16.02,14.78
N$X.2263  (via drill 0.2)  (1 unrouted)
  Bottom 0.2: 14.25,14.76 13.7,15.31 13.35,15.31
  other vias: 14.2,14.8
N$X.2264  (via drill 0.2)  (1 unrouted)
  Bottom 0.2: 14.18,12.17 13.63,12.72 13.29,12.72
  other vias: 14.13,12.15
N$X.2265  (via drill 0.2)  (1 unrouted)
  Bottom 0.2: 16.09,12.15 15.54,12.69 14.99,12.7
  other vias: 16.03,12.15
N$X.2266  (via drill 0.2)  (1 unrouted)
  Bottom 0.2: 17.83,12.12 17.28,12.66 16.66,12.73
  other vias: 17.77,12.14
N$X.2267  (via drill 0.2)  (1 unrouted)
  Bottom 0.2: v19.59,12.16 18.76,12.7 18.41,12.7
N$X.2268  (via drill 0.2)  (1 unrouted)
  Bottom 0.2: 21.4,12.07 20.86,12.62 20.2,12.77
  other vias: 21.4,12.15
N$X.2269  (via drill 0.2)  (1 unrouted)
  Bottom 0.2: 23.25,12.12 22.2,12.74 21.86,12.74
  other vias: 23.23,12.11
N$X.2270  (via drill 0.2)  (1 unrouted)
  Bottom 0.2: 24.99,17.37 24.45,17.91 23.88,17.92
  other vias: 24.98,17.34
N$X.2271  (via drill 0.2)  (1 unrouted)
  Bottom 0.2: 26.87,17.37 25.63,17.92 25.69,17.9
  other vias: 26.83,17.33
N$X.2273
  Bottom 0.2: 29.59,17.96 29.61,17.95
N$X.2278
  Bottom 0.2: 29.07,15.37 29.39,15.42
N$X.2279  (via drill 0.2)  (1 unrouted)
  Bottom 0.2: 28.69,14.76 27.95,15.46 27.61,15.46
  other vias: 28.64,14.78
N$X.2280  (via drill 0.2)  (1 unrouted)
  Bottom 0.2: 26.82,14.8 26.66,15.38 25.66,15.38
  other vias: 26.84,14.78
N$X.2281  (via drill 0.2)  (1 unrouted)
  Bottom 0.2: 24.89,14.85 24.3,15.31 23.95,15.31
  other vias: 24.98,14.79
N$X.2282  (via drill 0.2)  (1 unrouted)
  Bottom 0.2: 24.9,12.13 23.83,12.74 23.92,12.75
  other vias: 24.96,12.11
N$X.2283  (via drill 0.2)  (1 unrouted)
  Bottom 0.2: 26.66,12.11 26.02,12.76 25.67,12.76
  other vias: 26.75,12.13
N$X.2284  (via drill 0.2)  (1 unrouted)
  Bottom 0.2: 28.59,12.19 27.97,12.82 27.62,12.82
  other vias: 28.57,12.15
N$X.2330
  Bottom 0.2: 58.44,15.32 58.79,15.32
N$X.2332
  Bottom 0.2: 60.53,12.78 60.19,12.78
N$X.2333
  Bottom 0.2: 60.53,15.36 60.19,15.36
N$X.2334
  Bottom 0.2: 60.47,17.9 60.12,17.9
N$X.2335
  Bottom 0.2: 62.2,17.91 61.85,17.91
N$X.2336
  Bottom 0.2: 62.23,15.36 61.88,15.36
N$X.2337
  Bottom 0.2: 62.27,12.78 61.92,12.78
N$X.2338
  Bottom 0.2: 63.67,12.77 64.02,12.77
N$X.2339
  Bottom 0.2: 63.64,15.36 63.99,15.36
N$X.2340
  Bottom 0.2: 63.62,17.93 63.97,17.93
N$X.2341
  Bottom 0.2: 65.73,17.93 65.38,17.93
N$X.2342
  Bottom 0.2: 65.75,15.36 65.41,15.36
N$X.2343
  Bottom 0.2: 65.78,12.73 65.43,12.73
N$X.2344  (via drill 0.2)  (1 unrouted)
  Bottom 0.2: 68.05,17.39 67.5,17.93 67.16,17.93
  other vias: 68,17.37
N$X.2345  (via drill 0.2)  (1 unrouted)
  Bottom 0.2: 68.05,14.83 67.5,15.37 67.16,15.37
  other vias: 68,14.81
N$X.2346  (via drill 0.2)  (1 unrouted)
  Bottom 0.2: 68.08,12.22 67.53,12.77 67.18,12.77
  other vias: 68.03,12.2
N$X.2347  (via drill 0.2)  (1 unrouted)
  Bottom 0.2: 69.81,12.24 69.27,12.78 68.91,12.78
  other vias: 69.77,12.22
N$X.2348  (via drill 0.2)  (1 unrouted)
  Bottom 0.2: 69.88,14.8 69.33,15.34 68.98,15.34
  other vias: 69.81,14.82
N$X.2349  (via drill 0.2)  (1 unrouted)
  Bottom 0.2: 69.86,17.4 69.31,17.95 68.97,17.95
  other vias: 69.81,17.38
N$X.2350  (via drill 0.2)  (1 unrouted)
  Bottom 0.2: 71.58,17.42 71.04,17.96 70.69,17.96
  other vias: 71.54,17.4
N$X.2351  (via drill 0.2)  (1 unrouted)
  Bottom 0.2: 71.61,14.86 71.06,15.41 70.72,15.41
  other vias: 71.56,14.82
N$X.2352  (via drill 0.2)  (1 unrouted)
  Bottom 0.2: 71.61,12.13 71.06,12.68 70.72,12.68
  other vias: 71.54,12.17
N$X.2353  (via drill 0.2)  (1 unrouted)
  Bottom 0.2: 73.32,12.21 72.78,12.76 72.42,12.76
  other vias: 73.28,12.19
N$X.2354  (via drill 0.2)  (1 unrouted)
  Bottom 0.2: 73.3,14.83 72.76,15.37 72.41,15.37
  other vias: 73.26,14.81
N$X.2355  (via drill 0.2)  (1 unrouted)
  Bottom 0.2: 73.33,17.4 72.78,17.95 72.44,17.95
  other vias: 73.28,17.38
N$X.2356  (via drill 0.2)  (1 unrouted)
  Bottom 0.2: 75.05,17.4 74.51,17.95 74.16,17.95
  other vias: 75.01,17.38
N$X.2357  (via drill 0.2)  (1 unrouted)
  Bottom 0.2: 75.12,14.86 74.58,15.41 74.22,15.41
  other vias: 75.08,14.8
N$X.2358  (via drill 0.2)  (1 unrouted)
  Bottom 0.2: 75.05,12.22 74.51,12.77 74.16,12.77
  other vias: 75.01,12.2
N$X.2359  (via drill 0.2)  (1 unrouted)
  Bottom 0.2: 76.86,12.22 76.31,12.77 75.96,12.77
  other vias: 76.81,12.2
N$X.2360  (via drill 0.2)  (1 unrouted)
  Bottom 0.2: 76.83,14.84 76.28,15.38 75.94,15.38
  other vias: 76.78,14.82
N$X.2361  (via drill 0.2)  (1 unrouted)
  Bottom 0.2: 76.86,17.39 76.32,17.93 75.97,17.93
  other vias: 76.82,17.37
N$X.2362  (via drill 0.2)  (1 unrouted)
  Bottom 0.2: 78.59,12.24 78.05,12.78 77.69,12.78
  other vias: 78.55,12.22
N$X.2363  (via drill 0.2)  (1 unrouted)
  Bottom 0.2: 78.58,14.81 78.03,15.36 77.68,15.36
  other vias: 78.53,14.79
N$X.2364  (via drill 0.2)  (1 unrouted)
  Bottom 0.2: 78.56,17.4 78.02,17.95 77.67,17.95
  other vias: 78.52,17.38
N$X.2365  (via drill 0.2)  (1 unrouted)
  Bottom 0.2: 80.33,17.4 79.78,17.95 79.43,17.95
  other vias: 80.28,17.38
N$X.2366  (via drill 0.2)  (1 unrouted)
  Bottom 0.2: 80.33,14.86 79.79,15.41 79.44,15.41
  other vias: 80.29,14.84
N$X.2367  (via drill 0.2)  (1 unrouted)
  Bottom 0.2: 80.41,12.24 79.87,12.78 79.52,12.78
  other vias: 80.37,12.22
N$X.2368  (via drill 0.2)  (1 unrouted)
  Bottom 0.2: 82.15,12.25 81.61,12.79 81.25,12.79
  other vias: 82.11,12.23
N$X.2369  (via drill 0.2)  (1 unrouted)
  Bottom 0.2: 82.16,14.84 81.62,15.38 81.27,15.38
  other vias: 82.12,14.82
N$X.2370  (via drill 0.2)  (1 unrouted)
  Bottom 0.2: 82.11,17.36 81.56,17.91 81.22,17.91
  other vias: 82.06,17.34
N$X.2371  (via drill 0.2)  (1 unrouted)
  Bottom 0.2: 83.97,17.42 83.42,17.96 83.07,17.96
  other vias: 83.92,17.4
N$X.2372  (via drill 0.2)  (1 unrouted)
  Bottom 0.2: 84.03,14.89 83.48,15.44 83.14,15.44
  other vias: 83.98,14.87
N$X.2373  (via drill 0.2)  (1 unrouted)
  Bottom 0.2: 84.03,12.29 83.48,12.83 83.14,12.83
  other vias: 83.98,12.27
N$X.2374  (via drill 0.2)  (1 unrouted)
  Bottom 0.2: 85.89,12.29 85.35,12.83 85,12.83
  other vias: 85.85,12.27
N$X.2375  (via drill 0.2)  (1 unrouted)
  Bottom 0.2: 85.86,14.84 85.32,15.38 84.97,15.38
  other vias: 85.82,14.82
N$X.2376  (via drill 0.2)  (1 unrouted)
  Bottom 0.2: 85.84,17.4 85.3,17.95 84.94,17.95
  other vias: 85.8,17.38
N$X.2377  (via drill 0.2)  (1 unrouted)
  Bottom 0.2: 87.53,17.38 86.99,17.92 86.64,17.92
  other vias: 87.49,17.36
N$X.2378  (via drill 0.2)  (1 unrouted)
  Bottom 0.2: 87.51,14.84 86.97,15.38 86.61,15.38
  other vias: 87.47,14.82
N$X.2379  (via drill 0.2)  (1 unrouted)
  Bottom 0.2: 87.53,12.29 86.98,12.83 86.63,12.83
  other vias: 87.48,12.27
N$X.2380  (via drill 0.2)  (1 unrouted)
  Bottom 0.2: v89.25,12.25 88.7,12.79 88.35,12.79
N$X.2381  (via drill 0.2)  (1 unrouted)
  Bottom 0.2: 89.31,14.81 88.77,15.36 88.41,15.36
  other vias: 89.27,14.79
N$X.2382  (via drill 0.2)  (1 unrouted)
  Bottom 0.2: 89.33,17.4 88.79,17.95 88.44,17.95
  other vias: 89.29,17.38
N$X.2383  (via drill 0.2)  (1 unrouted)
  Bottom 0.2: 91.15,17.39 90.61,17.93 90.25,17.93
  other vias: 91.11,17.37
N$X.2384  (via drill 0.2)  (1 unrouted)
  Bottom 0.2: 91.08,14.84 90.54,15.38 90.19,15.38
  other vias: 91.04,14.82
N$X.2385  (via drill 0.2)  (1 unrouted)
  Bottom 0.2: 91.11,12.27 90.56,12.82 90.22,12.82
  other vias: 91.06,12.25
N$X.2386  (via drill 0.2)  (1 unrouted)
  Bottom 0.2: 92.92,17.4 92.38,17.95 92.03,17.95
  other vias: 92.88,17.38
N$X.2387  (via drill 0.2)  (1 unrouted)
  Bottom 0.2: 92.92,14.81 92.38,15.36 92.03,15.36
  other vias: 92.88,14.79
N$X.2388  (via drill 0.2)  (1 unrouted)
  Bottom 0.2: 92.9,12.3 92.36,12.85 92,12.85
  other vias: 92.86,12.28
N$X.2389  (via drill 0.2)  (1 unrouted)
  Bottom 0.2: 94.61,12.26 94.06,12.81 93.72,12.81
  other vias: 94.56,12.24
N$X.2390  (via drill 0.2)  (1 unrouted)
  Bottom 0.2: 96.38,12.31 95.83,12.86 95.48,12.86
  other vias: 96.33,12.29
N$X.2391  (via drill 0.2)  (1 unrouted)
  Bottom 0.2: 96.42,14.85 95.88,15.4 95.53,15.4
  other vias: 96.38,14.83
N$X.2392  (via drill 0.2)  (1 unrouted)
  Bottom 0.2: 96.39,17.39 95.85,17.93 95.5,17.93
  other vias: 96.35,17.37
N$X.2393  (via drill 0.2)  (1 unrouted)
  Bottom 0.2: 94.67,17.39 94.13,17.93 93.78,17.93
  other vias: 94.63,17.37
N$X.2394  (via drill 0.2)  (1 unrouted)
  Bottom 0.2: 94.64,14.81 94.1,15.36 93.75,15.36
  other vias: 94.6,14.79
N$X.2395  (via drill 0.2)  (1 unrouted)
  Bottom 0.2: 98.13,12.26 97.58,12.81 97.23,12.81
  other vias: 98.08,12.24
N$X.2396  (via drill 0.2)  (1 unrouted)
  Bottom 0.2: 98.17,14.85 97.62,15.4 97.28,15.4
  other vias: 98.12,14.83
N$X.2397  (via drill 0.2)  (1 unrouted)
  Bottom 0.2: 98.13,17.38 97.58,17.92 97.23,17.92
  other vias: 98.08,17.36
N$X.2398  (via drill 0.2)  (1 unrouted)
  Bottom 0.2: 99.84,17.42 99.3,17.96 98.94,17.96
  other vias: 99.8,17.4
N$X.2399  (via drill 0.2)  (1 unrouted)
  Bottom 0.2: 99.89,14.85 99.34,15.4 99,15.4
  other vias: 99.84,14.83
N$X.2400  (via drill 0.2)  (1 unrouted)
  Bottom 0.2: 99.86,12.25 99.32,12.79 98.97,12.79
  other vias: 99.82,12.23
N$X.2401  (via drill 0.2)  (1 unrouted)
  Bottom 0.2: 101.58,12.24 101.03,12.78 100.68,12.78
  other vias: 101.53,12.22
N$X.2402  (via drill 0.2)  (1 unrouted)
  Bottom 0.2: 101.61,14.88 101.07,15.42 100.72,15.42
  other vias: 101.57,14.86
N$X.2403  (via drill 0.2)  (1 unrouted)
  Bottom 0.2: 101.64,17.43 101.09,17.97 100.75,17.97
  other vias: 101.53,17.39
N$X.2406  (via drill 0.2)  (1 unrouted)
  Bottom 0.2: 112.04,17.47 111.5,18.01 111.14,18.01
  other vias: 112,17.45
N$X.2407  (via drill 0.2)  (1 unrouted)
  Bottom 0.2: 112.05,14.89 111.5,15.44 111.16,15.44
  other vias: 112,14.87
N$X.2408  (via drill 0.2)  (1 unrouted)
  Bottom 0.2: 112.09,12.24 111.55,12.78 111.19,12.78
  other vias: 112.02,12.17
N$X.2409  (via drill 0.2)  (1 unrouted)
  Bottom 0.2: 110.28,12.27 109.73,12.82 109.38,12.82
  other vias: 110.23,12.25
N$X.2410  (via drill 0.2)  (1 unrouted)
  Bottom 0.2: 110.24,14.89 109.69,15.44 109.34,15.44
  other vias: 110.19,14.87
N$X.2411  (via drill 0.2)  (1 unrouted)
  Bottom 0.2: 110.27,17.44 109.72,17.99 109.37,17.99
  other vias: 110.22,17.42
N$X.2412  (via drill 0.2)  (1 unrouted)
  Bottom 0.2: 108.52,17.47 107.97,18.01 107.62,18.01
  other vias: 108.45,17.43
N$X.2413  (via drill 0.2)  (1 unrouted)
  Bottom 0.2: 106.8,17.45 106.26,18 105.91,18
  other vias: 106.76,17.43
N$X.2414  (via drill 0.2)  (1 unrouted)
  Bottom 0.2: 105.07,17.45 104.53,18 104.17,18
  other vias: 105.03,17.43
N$X.2415  (via drill 0.2)  (1 unrouted)
  Bottom 0.2: 103.35,17.47 102.8,18.01 102.45,18.01
  other vias: 103.3,17.45
N$X.2416  (via drill 0.2)  (1 unrouted)
  Bottom 0.2: 103.33,14.89 102.78,15.44 102.43,15.44
  other vias: 103.28,14.87
N$X.2417  (via drill 0.2)  (1 unrouted)
  Bottom 0.2: 105.06,14.85 104.52,15.4 104.16,15.4
  other vias: 105.02,14.83
N$X.2418  (via drill 0.2)  (1 unrouted)
  Bottom 0.2: 106.73,14.9 106.19,15.45 105.83,15.45
  other vias: 106.69,14.88
N$X.2419  (via drill 0.2)  (1 unrouted)
  Bottom 0.2: 108.44,14.89 107.89,15.44 107.55,15.44
  other vias: 108.39,14.87
N$X.2420  (via drill 0.2)  (1 unrouted)
  Bottom 0.2: 108.45,12.22 107.91,12.77 107.55,12.77
  other vias: 108.41,12.2
N$X.2421  (via drill 0.2)  (1 unrouted)
  Bottom 0.2: 106.78,12.18 106.23,12.73 105.89,12.73
  other vias: 106.73,12.16
N$X.2422  (via drill 0.2)  (1 unrouted)
  Bottom 0.2: 105.07,12.13 104.53,12.68 104.17,12.68
  other vias: 105.03,12.11
N$X.2423  (via drill 0.2)  (1 unrouted)
  Bottom 0.2: 103.39,12.24 102.84,12.78 102.5,12.78
  other vias: 103.24,12.22
N$X.2426  (1 unrouted)
N$X.2428  (via drill 0.2)  (1 unrouted)
  Bottom 0.2: 112.01,19.91 111.47,20.46 111.11,20.46
  other vias: 111.97,19.89
N$X.2429  (via drill 0.2)  (1 unrouted)
  Bottom 0.2: 111.98,22.48 111.44,23.02 111.09,23.02
  other vias: 111.94,22.46
N$X.2430  (via drill 0.2)  (1 unrouted)
  Bottom 0.2: 112,25.12 111.45,25.67 111.11,25.67
  other vias: 111.95,25.1
N$X.2431  (via drill 0.2)  (1 unrouted)
  Bottom 0.2: 110.28,25.11 109.73,25.65 109.38,25.65
  other vias: 110.23,25.09
N$X.2432  (via drill 0.2)  (1 unrouted)
  Bottom 0.2: 110.27,22.48 109.72,23.02 109.37,23.02
  other vias: 110.22,22.46
N$X.2433  (via drill 0.2)  (1 unrouted)
  Bottom 0.2: 110.28,19.88 109.73,20.42 109.38,20.42
  other vias: 110.23,19.86
N$X.2434  (via drill 0.2)  (1 unrouted)
  Bottom 0.2: 108.55,22.5 108.01,23.05 107.66,23.05
  other vias: 108.51,22.48
N$X.2435  (via drill 0.2)  (1 unrouted)
  Bottom 0.2: 106.8,22.52 106.25,23.06 105.9,23.06
  other vias: 106.75,22.5
N$X.2436  (via drill 0.2)  (1 unrouted)
  Bottom 0.2: 105,22.5 104.53,23.13 104.17,23.13
  other vias: 105,22.47
N$X.2437  (via drill 0.2)  (1 unrouted)
  Bottom 0.2: 103.33,22.53 102.79,23.08 102.44,23.08
  other vias: 103.29,22.51
N$X.2438  (via drill 0.2)  (1 unrouted)
  Bottom 0.2: 103.31,19.95 102.77,20.5 102.41,20.5
  other vias: 103.27,19.93
N$X.2439  (via drill 0.2)  (1 unrouted)
  Bottom 0.2: 105.12,19.95 104.58,20.5 104.23,20.5
  other vias: 105.08,19.93
N$X.2440  (via drill 0.2)  (1 unrouted)
  Bottom 0.2: 106.8,19.88 106.26,20.42 105.91,20.42
  other vias: 106.76,19.86
N$X.2441  (via drill 0.2)  (1 unrouted)
  Bottom 0.2: 108.54,19.9 108,20.45 107.64,20.45
  other vias: 108.5,19.88
N$X.2442  (via drill 0.2)  (1 unrouted)
  Bottom 0.2: 108.55,25.16 108,25.71 107.66,25.71
  other vias: 108.5,25.06
N$X.2443  (via drill 0.2)  (1 unrouted)
  Bottom 0.2: 106.76,25.12 106.22,25.66 105.86,25.66
  other vias: 106.72,25.1
N$X.2444  (via drill 0.2)  (1 unrouted)
  Bottom 0.2: 105.06,25.12 104.52,25.66 104.16,25.66
  other vias: 105.02,25.1
N$X.2445  (via drill 0.2)  (1 unrouted)
  Bottom 0.2: 103.29,25.14 102.75,25.68 102.39,25.68
  other vias: 103.25,25.12
N$X.2446  (via drill 0.2)  (1 unrouted)
  Bottom 0.2: 14.23,22.52 13.68,23.07 13.33,23.07
  other vias: 14.18,22.5
N$X.2447  (via drill 0.2)  (1 unrouted)
  Bottom 0.2: 16.12,22.4 15.58,22.94 15.01,23.04
  other vias: 16.02,22.45
N$X.2448  (via drill 0.2)  (1 unrouted)
  Bottom 0.2: v17.8,22.44 17.03,23.07 16.68,23.07
N$X.2449  (via drill 0.2)  (1 unrouted)
  Bottom 0.2: 19.65,22.44 19.1,22.99 18.38,23.04
  other vias: 19.62,22.46
N$X.2450  (via drill 0.2)  (1 unrouted)
  Bottom 0.2: 21.37,25.09 20.82,25.64 20.21,25.71
  other vias: 21.38,25.08
N$X.2451  (via drill 0.2)  (1 unrouted)
  Bottom 0.2: 23.16,25.07 22.33,25.75 21.98,25.75
  other vias: 23.19,25.05
N$X.2452  (via drill 0.2)  (1 unrouted)
  Bottom 0.2: 24.88,25.11 24.33,25.65 23.65,25.66
  other vias: 24.91,25.05
N$X.2453  (via drill 0.2)  (1 unrouted)
  Bottom 0.2: 26.75,25.16 26.2,25.71 25.47,25.73
  other vias: 26.8,25.07
N$X.2454  (via drill 0.2)  (1 unrouted)
  Bottom 0.2: 28.61,25.1 28.06,25.64 27.26,25.66
  other vias: 28.64,25.07
N$X.2455  (via drill 0.2)  (1 unrouted)
  Bottom 0.2: v28.61,22.44 27.63,23.07 27.28,23.07
N$X.2456  (via drill 0.2)  (1 unrouted)
  Bottom 0.2: 26.7,22.49 25.93,23.02 25.58,23.02
  other vias: 26.74,22.44
N$X.2457  (via drill 0.2)  (1 unrouted)
  Bottom 0.2: 24.96,22.49 24.14,23.07 23.79,23.07
  other vias: 25.01,22.44
N$X.2458  (via drill 0.2)  (1 unrouted)
  Bottom 0.2: 23.21,22.47 22.4,23.09 22.05,23.09
  other vias: 23.24,22.46
N$X.2459  (via drill 0.2)  (1 unrouted)
  Bottom 0.2: 21.3,22.44 20.54,23.09 20.19,23.09
  other vias: 21.34,22.44
N$X.2460  (via drill 0.2)  (1 unrouted)
  Bottom 0.2: 19.65,25.07 19.1,25.61 18.42,25.68
  other vias: 19.61,25.09
N$X.2461  (via drill 0.2)  (1 unrouted)
  Bottom 0.2: 17.74,25.08 17,25.71 16.65,25.71
  other vias: 17.77,25.04
N$X.2462  (via drill 0.2)  (1 unrouted)
  Bottom 0.2: 15.9,25.14 15.36,25.68 15.01,25.68
  other vias: 16.03,25.01
N$X.2463  (via drill 0.2)  (1 unrouted)
  Bottom 0.2: 19.49,19.87 18.73,20.57 18.38,20.57
  other vias: 19.57,19.89
N$X.2464  (via drill 0.2)  (1 unrouted)
  Bottom 0.2: 21.15,19.98 20.61,20.52 20.26,20.52
  other vias: 21.31,19.89
N$X.2465  (via drill 0.2)  (1 unrouted)
  Bottom 0.2: v23.24,19.87 22.36,20.61 22,20.61
N$X.2466  (via drill 0.2)  (1 unrouted)
  Bottom 0.2: 24.95,19.88 24.12,20.52 23.77,20.52
  other vias: 24.98,19.87
N$X.2467  (via drill 0.2)  (1 unrouted)
  Bottom 0.2: 26.68,19.93 25.95,20.57 25.61,20.57
  other vias: 26.76,19.89
N$X.2468  (via drill 0.2)  (1 unrouted)
  Bottom 0.2: 17.81,19.87 17.27,20.42 16.63,20.45
  other vias: 17.82,19.89
N$X.2469  (via drill 0.2)  (1 unrouted)
  Bottom 0.2: 16,19.87 15.31,20.52 14.96,20.52
  other vias: 16.02,19.89
N$X.2470  (via drill 0.2)  (1 unrouted)
  Bottom 0.2: 14.25,19.93 13.7,20.47 13.35,20.47
  other vias: 14.2,19.91
N$X.2473
  Bottom 0.2: 29.29,23 29.15,23.01
N$X.2474  (via drill 0.2)  (2 unrouted)
  Bottom 0.2: 29.53,25.63 29.18,25.63 | 30.42,25.07 29.76,25.73 29.45,25.73
  other vias: 30.4,25.05
N$X.2475  (via drill 0.2)  (1 unrouted)
  Bottom 0.2: 32.24,25.09 31.54,25.79 31.12,25.79
  other vias: 32.21,25.07
N$X.2478  (via drill 0.2)  (1 unrouted)
  Bottom 0.2: v33.95,25.09 33.3,25.75 32.94,25.75
N$X.2479  (via drill 0.2)  (1 unrouted)
  Bottom 0.2: 35.8,25.05 35.12,25.73 34.94,25.73
  other vias: 35.78,25.05
N$X.2480  (via drill 0.2)  (1 unrouted)
  Bottom 0.2: v37.57,25.05 36.85,25.77 36.61,25.77
N$X.2481  (via drill 0.2)  (1 unrouted)
  Bottom 0.2: 39.42,25.07 38.78,25.71 38.58,25.71
  other vias: 39.4,25.07
N$X.2521
  Bottom 0.2: 58.45,20.45 58.8,20.45
N$X.2527
  Bottom 0.2: 62.17,20.52 61.82,20.52
N$X.2532
  Bottom 0.2: 63.66,20.43 64.01,20.43
N$X.2533
  Bottom 0.2: 65.7,20.52 65.36,20.52
N$X.2534  (via drill 0.2)  (1 unrouted)
  Bottom 0.2: 68.04,19.86 67.5,20.41 67.14,20.41
  other vias: 68,19.84
N$X.2535  (via drill 0.2)  (1 unrouted)
  Bottom 0.2: 68.25,22.43 67.7,22.98 67.36,22.98
  other vias: 68.28,22.46
N$X.2536  (via drill 0.2)
  Bottom 0.2: v68.2,25.09 67.66,25.64 67.3,25.64
N$X.2537  (via drill 0.2)  (1 unrouted)
  Bottom 0.2: 70.02,25.07 69.47,25.62 69.12,25.62
  other vias: 69.97,25.05
N$X.2538  (via drill 0.2)  (1 unrouted)
  Bottom 0.2: 70.04,22.52 69.5,23.07 69.14,23.07
  other vias: 70,22.5
N$X.2539  (via drill 0.2)  (1 unrouted)
  Bottom 0.2: 69.86,19.93 69.31,20.47 68.96,20.47
  other vias: 69.81,19.91
N$X.2540  (via drill 0.2)  (1 unrouted)
  Bottom 0.2: 71.62,19.91 71.08,20.45 70.72,20.45
  other vias: 71.58,19.89
N$X.2541  (via drill 0.2)  (1 unrouted)
  Bottom 0.2: 71.83,22.55 71.28,23.09 70.94,23.09
  other vias: 71.78,22.53
N$X.2542  (via drill 0.2)  (1 unrouted)
  Bottom 0.2: 71.8,25.14 71.26,25.68 70.91,25.68
  other vias: 71.76,25.12
N$X.2543  (via drill 0.2)  (1 unrouted)
  Bottom 0.2: 73.55,25.16 73,25.71 72.66,25.71
  other vias: 73.5,25.14
N$X.2544  (via drill 0.2)  (1 unrouted)
  Bottom 0.2: 73.57,22.48 73.03,23.02 72.67,23.02
  other vias: 73.53,22.46
N$X.2545  (via drill 0.2)  (1 unrouted)
  Bottom 0.2: 73.36,19.91 72.82,20.45 72.47,20.45
  other vias: 73.32,19.89
N$X.2546  (via drill 0.2)  (1 unrouted)
  Bottom 0.2: 75.06,19.95 74.52,20.5 74.17,20.5
  other vias: 75.02,19.93
N$X.2547  (via drill 0.2)  (1 unrouted)
  Bottom 0.2: 75.3,22.45 74.75,23 74.4,23
  other vias: 75.25,22.43
N$X.2548  (via drill 0.2)  (1 unrouted)
  Bottom 0.2: 75.41,25.14 74.86,25.68 74.52,25.68
  other vias: 75.36,25.12
N$X.2549  (via drill 0.2)  (1 unrouted)
  Bottom 0.2: 77.06,25.09 76.52,25.64 76.16,25.64
  other vias: 77.02,25.07
N$X.2550  (via drill 0.2)  (1 unrouted)
  Bottom 0.2: 77.04,22.5 76.5,23.04 76.14,23.04
  other vias: 77,22.48
N$X.2551  (via drill 0.2)  (1 unrouted)
  Bottom 0.2: 78.83,25.12 78.28,25.66 77.94,25.66
  other vias: 78.78,25.1
N$X.2552  (via drill 0.2)  (1 unrouted)
  Bottom 0.2: 78.76,22.48 78.22,23.02 77.86,23.02
  other vias: 78.72,22.46
N$X.2553  (via drill 0.2)  (1 unrouted)
  Bottom 0.2: 78.53,19.88 77.98,20.43 77.64,20.43
  other vias: 78.48,19.86
N$X.2554  (via drill 0.2)  (1 unrouted)
  Bottom 0.2: 80.34,19.88 79.8,20.43 79.44,20.43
